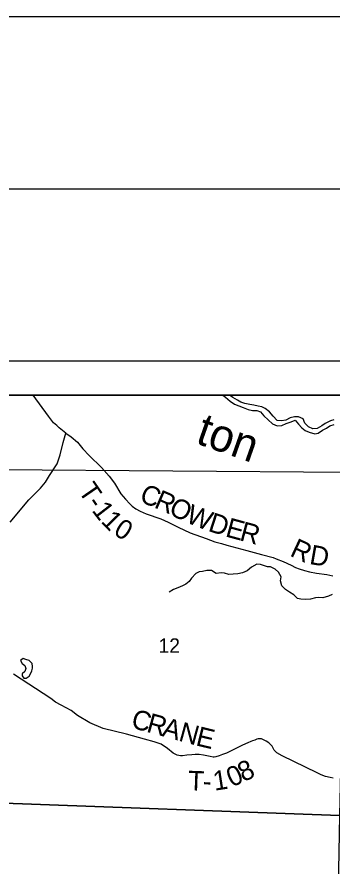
# Model space of a CAD drawing. Extents: x -1.2 to 34, y -8.5 to 22.
# Drawn here: x 3.539 to 4.454, y 19.531 to 22 of the extents above; entities that cross this region are included whole.
import ezdxf

# ---------------------------------------------------------------- set-up
doc = ezdxf.new("R2010")
doc.units = 0
for name, color, linetype in [('GM_X_Major_River', 7, 'Continuous'), ('GM_X_Major_River_Text', 7, 'Continuous'), ('GM_X_Minor_Lake', 7, 'Continuous'), ('GM_X_Minor_River', 7, 'Continuous'), ('GM_X_Section', 7, 'Continuous'), ('GM_X_Section_Text', 7, 'Continuous'), ('GM_X_Township_Road', 7, 'Continuous'), ('GM_X_Township_Road_Text', 7, 'Continuous'), ('GM_X_Unincorporated_Text', 7, 'Continuous'), ('SH_Border', 7, 'Continuous'), ('SH_Cut_Line', 7, 'Continuous'), ('SH_Data', 7, 'Continuous')]:
    doc.layers.add(name, color=color, linetype=linetype)

msp = doc.modelspace()

# ---------------------------------------------------------------- linework, layer by layer
at = {"layer": 'GM_X_Major_River'}
for points in [[(4.1365, 20.9), (4.1441, 20.8949), (4.1576, 20.883), (4.1703, 20.8741), (4.1833, 20.8694), (4.1959, 20.8643), (4.2097, 20.8585), (4.2223, 20.856), (4.2349, 20.8555), (4.2456, 20.8518), (4.2556, 20.8406), (4.2804, 20.8168), (4.2942, 20.8109), (4.3082, 20.8119), (4.3206, 20.8182), (4.3346, 20.823), (4.3471, 20.8278), (4.3564, 20.8158), (4.3657, 20.8057), (4.3754, 20.7975), (4.3876, 20.7924), (4.4033, 20.7881), (4.4131, 20.7902), (4.4263, 20.7984), (4.4372, 20.8042), (4.447, 20.8112), (4.4598, 20.8149)], [(4.4592, 20.8285), (4.4494, 20.8257), (4.4339, 20.8182), (4.4242, 20.8108), (4.4106, 20.803), (4.3981, 20.8024), (4.3851, 20.8079), (4.375, 20.8191), (4.3695, 20.8319), (4.3568, 20.8374), (4.345, 20.8372), (4.3325, 20.8347), (4.3197, 20.8273), (4.3068, 20.8256), (4.2947, 20.8269), (4.283, 20.8388), (4.2722, 20.8515), (4.2595, 20.8619), (4.2495, 20.8667), (4.2396, 20.8684), (4.2262, 20.8712), (4.2148, 20.8733), (4.2007, 20.8758), (4.1888, 20.8797), (4.1789, 20.8856), (4.1654, 20.8937), (4.1559, 20.9)]]:
    msp.add_lwpolyline(points, dxfattribs=at)
at = {"layer": 'GM_X_Minor_Lake'}
for points in [[(3.5631, 20.1088), (3.5646, 20.1051), (3.5612, 20.0963), (3.5537, 20.0898), (3.5537, 20.0841), (3.558, 20.0774), (3.5656, 20.0778), (3.5739, 20.0836), (3.5787, 20.0923), (3.5813, 20.0984), (3.5835, 20.106), (3.5839, 20.1117), (3.5823, 20.1201), (3.5738, 20.1291), (3.5647, 20.132), (3.5563, 20.135), (3.5484, 20.1292)], [(3.5484, 20.1292), (3.5538, 20.1202), (3.5611, 20.1138), (3.5631, 20.1088)]]:
    msp.add_lwpolyline(points, dxfattribs=at)
at = {"layer": 'GM_X_Minor_River'}
for points in [[(4.4537, 20.3211), (4.4431, 20.3157), (4.4272, 20.311), (4.4158, 20.3117), (4.406, 20.3108), (4.3908, 20.3069), (4.3775, 20.306), (4.3635, 20.3074), (4.3539, 20.3089), (4.3432, 20.3201), (4.3298, 20.3276), (4.3188, 20.3347), (4.3077, 20.346), (4.3045, 20.3608), (4.3055, 20.3718), (4.2986, 20.3854), (4.2886, 20.394), (4.2753, 20.4007), (4.2658, 20.4014), (4.246, 20.4081), (4.2357, 20.4084), (4.2202, 20.4006), (4.2074, 20.3891), (4.1934, 20.3837), (4.1805, 20.3806), (4.1661, 20.3797), (4.1539, 20.3792), (4.1413, 20.3825), (4.1318, 20.3839), (4.117, 20.3815), (4.1033, 20.3905), (4.0904, 20.3908), (4.0771, 20.3873)], [(4.0771, 20.3873), (4.0676, 20.3864), (4.0578, 20.3814), (4.0458, 20.3684), (4.039, 20.3585), (4.0288, 20.3504), (4.019, 20.3454), (4.0061, 20.3396), (3.9933, 20.3349), (3.9808, 20.3276)]]:
    msp.add_lwpolyline(points, dxfattribs=at)
at = {"layer": 'GM_X_Section'}
for points in [[(4.504, 20.9), (3.4869, 20.9), (3.4838, 20.6845), (4.4978, 20.6761)], [(3.4838, 20.6845), (4.4978, 20.6761), (4.4756, 19.6778), (3.4745, 19.7148)], [(3.4745, 19.7148), (4.4756, 19.6778), (4.4573, 18.6708), (3.4647, 18.6909)]]:
    msp.add_lwpolyline(points, close=True, dxfattribs=at)
at = {"layer": 'GM_X_Township_Road'}
for points in [[(3.6805, 20.7901), (3.6611, 20.8052), (3.654, 20.8117), (3.6449, 20.8199), (3.6304, 20.8391), (3.5852, 20.9)], [(3.5184, 20.531), (3.5731, 20.5963), (3.6072, 20.6303), (3.621, 20.6473), (3.6333, 20.6666), (3.6555, 20.7006), (3.6642, 20.727), (3.6727, 20.7624), (3.6805, 20.7901)], [(3.6805, 20.7901), (3.6963, 20.7794), (3.7146, 20.764), (3.73, 20.7446), (3.7483, 20.725), (3.7839, 20.6902), (3.806, 20.6652), (3.8214, 20.6445), (3.8401, 20.6137), (3.8533, 20.5975), (3.8668, 20.584), (3.873, 20.5777), (3.8841, 20.5698), (3.8965, 20.5628), (3.9137, 20.5556), (3.9565, 20.5405), (3.9777, 20.5309), (4.0063, 20.516), (4.0418, 20.5001), (4.0877, 20.4834), (4.1131, 20.474), (4.1322, 20.4688), (4.1482, 20.4638), (4.206, 20.4484), (4.2488, 20.4372), (4.2825, 20.4283), (4.2915, 20.4247), (4.312, 20.4169), (4.3348, 20.4058), (4.348, 20.3996), (4.3578, 20.3952), (4.374, 20.39), (4.3882, 20.3864), (4.4084, 20.3823), (4.4388, 20.3784), (4.4556, 20.3751)], [(4.4575, 19.787), (4.4482, 19.7883), (4.4346, 19.791), (4.4218, 19.7959), (4.4105, 19.8016), (4.3089, 19.8511), (4.2936, 19.8599), (4.286, 19.8682), (4.2794, 19.8795), (4.2702, 19.8889), (4.2625, 19.8946), (4.2531, 19.8991), (4.2485, 19.9005), (4.2439, 19.901), (4.2393, 19.9007), (4.2356, 19.8996), (4.2294, 19.8974), (4.2224, 19.8951), (4.218, 19.8933), (4.2093, 19.8895), (4.1935, 19.8823), (4.1685, 19.8699), (4.1471, 19.8596), (4.1356, 19.8557), (4.1256, 19.8518), (4.1161, 19.8485), (4.1118, 19.8474), (4.1082, 19.8477), (4.0999, 19.8492), (4.0901, 19.8511), (4.0801, 19.8536), (4.0679, 19.8557), (4.0561, 19.8551), (4.046, 19.8546), (4.0322, 19.8538), (4.0198, 19.8516), (4.0131, 19.8512), (4.0034, 19.8536), (3.9925, 19.8597), (3.9756, 19.8727), (3.957, 19.8852), (3.9371, 19.8921), (3.9087, 19.8996), (3.8563, 19.9145), (3.7893, 19.9312), (3.7497, 19.9471), (3.7147, 19.9683), (3.6959, 19.9835), (3.6671, 19.9985), (3.6501, 20.0073), (3.6365, 20.0182), (3.5287, 20.0888)]]:
    msp.add_lwpolyline(points, dxfattribs=at)
at = {"layer": 'GM_X_Unincorporated_Text'}
msp.add_lwpolyline([(8.4143, 20.9), (2.465, 20.9), (2.4644, 20.6742), (2.4628, 20.1657), (2.4414, 19.0677), (2.4258, 17.6899), (2.8968, 17.6806), (3.3984, 17.6707), (4.1759, 17.654), (4.4093, 17.6489), (4.6867, 17.6371)], dxfattribs=at)
at = {"layer": 'SH_Border'}
msp.add_lwpolyline([(1.5, 21.5), (33.5, 21.5), (33.5, 0.5), (1.5, 0.5)], close=True, dxfattribs=at)
at = {"layer": 'SH_Cut_Line'}
msp.add_lwpolyline([(0, 0), (34, 0), (34, 22), (0, 22)], close=True, dxfattribs=at)
msp.add_lwpolyline([(8.9, 20.9), (2.465, 20.9), (2.4644, 20.6742), (2.4628, 20.1657), (2.4414, 19.0677), (2.4258, 17.6899), (2.8968, 17.6806), (3.3984, 17.6707), (4.1759, 17.654), (4.4093, 17.6489), (4.6867, 17.6371)], dxfattribs=at)
at = {"layer": 'SH_Data'}
for p, q in [((2, 21), (9, 21)), ((2.1, 20.9), (8.9, 20.9))]:
    msp.add_line(p, q, dxfattribs=at)

# ---------------------------------------------------------------- texts
at = {"layer": 'GM_X_Major_River_Text'}
msp.add_text('ton', height=0.0947, rotation=340.6595, dxfattribs=at).set_placement((4.0541, 20.7616))
at = {"layer": 'GM_X_Section_Text'}
msp.add_text('12', height=0.04186, rotation=0, dxfattribs=at).set_placement((3.9497, 20.1512))
at = {"layer": 'GM_X_Township_Road_Text'}
for s, rotation, p in [('T', 304.5697, (3.7148, 20.6216)), ('C', 337.4108, (3.8912, 20.5923)), ('R', 336.6474, (3.9341, 20.5745)), ('-', 304.8825, (3.7391, 20.5863)), ('O', 333.2191, (3.9762, 20.5564)), ('1', 307.6149, (3.7542, 20.5648)), ('W', 338.5253, (4.026, 20.5315)), ('1', 314.1011, (3.7801, 20.5318)), ('D', 342.2379, (4.0911, 20.506)), ('E', 344.8007, (4.1414, 20.49)), ('0', 327.6955, (3.8158, 20.4974)), ('R', 345.0105, (4.1826, 20.4788)), ('R', 335.172, (4.3285, 20.4342)), ('D', 350.0658, (4.3859, 20.4098)), ('C', 345.0081, (3.8672, 19.9339)), ('R', 344.5953, (3.9121, 19.9219)), ('A', 344.5938, (3.9571, 19.9095)), ('N', 344.6417, (4.0054, 19.8962)), ('E', 346.3372, (4.0554, 19.8825)), ('8', 25.5761, (4.1964, 19.7745)), ('T', 357.9639, (4.035, 19.7515)), ('1', 8.7869, (4.1124, 19.7499)), ('0', 23.5354, (4.1623, 19.7596)), ('-', 358.0748, (4.0776, 19.75))]:
    msp.add_text(s, height=0.0568, rotation=rotation, dxfattribs=at).set_placement(p)

doc.saveas('drawing.dxf')
